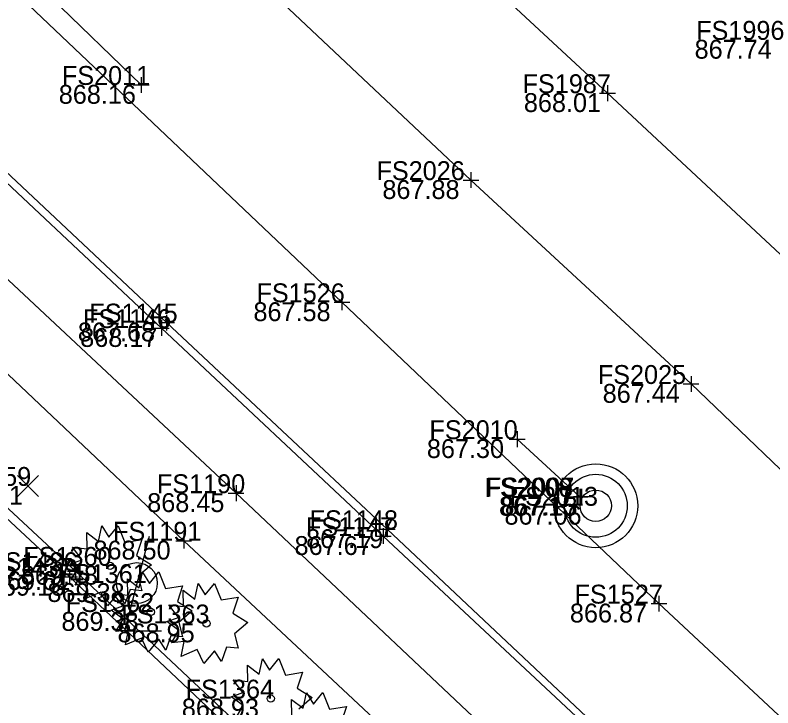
# Model space of a CAD drawing. Extents: x 1479420 to 1479833, y 379731 to 380103.
# Drawn here: x 1479671.72 to 1479719.92, y 379820.06 to 379864.1 of the extents above; entities that cross this region are included whole.
import ezdxf

# ---------------------------------------------------------------- set-up
doc = ezdxf.new("R2010")
doc.units = 0
for name, color, linetype in [('DR_X_Cells', 7, 'Continuous'), ('GK_Drainage_Nodes', 7, 'Continuous'), ('LT_X_Poles', 7, 'Continuous'), ('PM_X_Channelizing_Line', 7, 'Continuous'), ('PM_X_CL_Double_Solid', 7, 'Continuous'), ('PM_X_Lane_Line', 7, 'Continuous'), ('PV_X_Curb', 7, 'Continuous'), ('PV_X_Walk', 7, 'Continuous'), ('SV_X_Random_Point', 7, 'Continuous'), ('SV_X_Shot_Marker', 7, 'Continuous'), ('SV_X_Text_Elevation', 7, 'Continuous'), ('SV_X_Text_Name', 7, 'Continuous'), ('UT_X_Water', 7, 'Continuous'), ('VG_X_Cells', 7, 'Continuous')]:
    doc.layers.add(name, color=color, linetype=linetype)

msp = doc.modelspace()

# ---------------------------------------------------------------- linework, layer by layer
at = {"layer": 'DR_X_Cells'}
for radius in [2.667, 2, 1]:
    msp.add_circle((1479708.658, 379832.907), radius, dxfattribs=at)
at = {"layer": 'GK_Drainage_Nodes'}
for p, q in [((1479708.658, 379834.907), (1479708.658, 379834.907)), ((1479708.658, 379832.907), (1479708.658, 379832.907)), ((1479708.658, 379832.907), (1479708.658, 379832.907)), ((1479708.658, 379832.907), (1479708.658, 379832.907)), ((1479708.658, 379830.907), (1479708.658, 379830.907))]:
    msp.add_line(p, q, dxfattribs=at)
msp.add_circle((1479708.658, 379832.907), 2, dxfattribs=at)
at = {"layer": 'LT_X_Poles'}
msp.add_lwpolyline([(1479680.246, 379830.943), (1479678.671, 379824.958), (1479681.034, 379824.958)], dxfattribs=at)
msp.add_circle((1479679.459, 379827.99), 1.3, dxfattribs=at)
at = {"layer": 'PM_X_Channelizing_Line'}
msp.add_lwpolyline([(1479685.324, 379881.456), (1479709.405, 379859.144), (1479736.1, 379834.256)], dxfattribs=at)
at = {"layer": 'PM_X_CL_Double_Solid'}
msp.add_lwpolyline([(1479794.219, 379768.772), (1479779.093, 379781.771), (1479763.159, 379795.427), (1479746.619, 379810.624), (1479732.239, 379823.873), (1479714.719, 379840.653), (1479700.713, 379853.615), (1479677.934, 379875.066)], dxfattribs=at)
at = {"layer": 'PM_X_Lane_Line'}
for p, q in [((1479679.734, 379859.668), (1479671.915, 379867.241)), ((1479707.65, 379833.476), (1479703.657, 379837.143))]:
    msp.add_line(p, q, dxfattribs=at)
at = {"layer": 'PV_X_Curb'}
for points in [[(1479752.341, 379756.82), (1479734.895, 379773.493), (1479717.229, 379789.662), (1479699.298, 379806.401), (1479688.16, 379794.934), (1479685.526, 379793.897), (1479682.733, 379795.157), (1479681.263, 379797.549), (1479682.493, 379800.746), (1479693.462, 379811.911), (1479675.554, 379828.75), (1479655.832, 379847.057), (1479640.191, 379861.808), (1479628.558, 379849), (1479624.614, 379847.663), (1479622.46, 379848.585), (1479618.996, 379850.857), (1479611.825, 379854.437), (1479601.319, 379856.891), (1479590.521, 379858.038)], [(1479751.933, 379756.628), (1479734.447, 379772.976), (1479716.701, 379789.463), (1479699.4, 379805.742), (1479688.561, 379794.786), (1479685.717, 379793.294), (1479682.291, 379794.8), (1479680.73, 379797.254), (1479682.169, 379801.189), (1479692.652, 379811.907), (1479675.183, 379828.391), (1479655.51, 379846.682), (1479640.151, 379860.926), (1479629.134, 379848.869), (1479624.571, 379847.215), (1479622.228, 379847.911), (1479618.757, 379850.398), (1479611.519, 379853.97), (1479601.347, 379856.369), (1479590.364, 379857.442)], [(1479667.529, 379857.521), (1479681.356, 379844.557), (1479695.384, 379831.416), (1479709.512, 379818.131), (1479724.003, 379804.728), (1479730.662, 379798.272), (1479750.68, 379779.69), (1479759.253, 379771.893), (1479760.555, 379770.78), (1479775.03, 379758.526), (1479788.183, 379747.585), (1479800.537, 379737.251), (1479801.677, 379736.292)], [(1479667.239, 379857.122), (1479681.024, 379844.208), (1479695.135, 379830.978), (1479709.331, 379817.708), (1479723.729, 379804.193), (1479729.719, 379798.6), (1479748.963, 379780.548), (1479759.065, 379771.485), (1479760.185, 379770.473), (1479774.837, 379758.13), (1479787.835, 379747.16), (1479799.962, 379737.109), (1479801.3, 379736.045)]]:
    msp.add_lwpolyline(points, dxfattribs=at)
at = {"layer": 'PV_X_Walk'}
for points in [[(1479760.141, 379765.373), (1479756.862, 379768.221), (1479747.096, 379776.51), (1479736.047, 379786.698), (1479722.324, 379799.574), (1479705.728, 379814.894), (1479685.769, 379833.708), (1479660.411, 379857.395)], [(1479801.031, 379735.954), (1479794.804, 379736.123), (1479792.191, 379733.142), (1479782.769, 379741.06), (1479767.055, 379754.294), (1479759.061, 379761.026), (1479757.309, 379762.481), (1479754.256, 379765.105), (1479744.261, 379773.561), (1479732.859, 379783.688), (1479719.35, 379796.384), (1479703.027, 379811.462), (1479682.443, 379830.686), (1479657.296, 379854.468)]]:
    msp.add_lwpolyline(points, dxfattribs=at)
at = {"layer": 'SV_X_Random_Point'}
for p, q in [((1479671.864, 379833.504), (1479673.198, 379834.839)), ((1479671.864, 379834.839), (1479673.198, 379833.504))]:
    msp.add_line(p, q, dxfattribs=at)
at = {"layer": 'SV_X_Shot_Marker'}
for p, q in [((1479679.734, 379860.168), (1479679.734, 379859.168)), ((1479679.234, 379859.668), (1479680.234, 379859.668)), ((1479679.734, 379859.668), (1479679.734, 379859.668)), ((1479709.405, 379859.644), (1479709.405, 379858.644)), ((1479708.905, 379859.144), (1479709.905, 379859.144)), ((1479709.405, 379859.144), (1479709.405, 379859.144)), ((1479700.713, 379854.115), (1479700.713, 379853.115)), ((1479700.213, 379853.615), (1479701.213, 379853.615)), ((1479700.713, 379853.615), (1479700.713, 379853.615)), ((1479692.509, 379846.347), (1479692.509, 379845.347)), ((1479692.009, 379845.847), (1479693.009, 379845.847)), ((1479692.509, 379845.847), (1479692.509, 379845.847)), ((1479681.356, 379845.057), (1479681.356, 379844.057)), ((1479680.856, 379844.557), (1479681.856, 379844.557)), ((1479681.024, 379844.708), (1479681.024, 379843.708)), ((1479681.356, 379844.557), (1479681.356, 379844.557)), ((1479680.524, 379844.208), (1479681.524, 379844.208)), ((1479681.024, 379844.208), (1479681.024, 379844.208)), ((1479714.719, 379841.153), (1479714.719, 379840.153)), ((1479714.219, 379840.653), (1479715.219, 379840.653)), ((1479714.719, 379840.653), (1479714.719, 379840.653)), ((1479703.657, 379837.643), (1479703.657, 379836.643)), ((1479703.157, 379837.143), (1479704.157, 379837.143)), ((1479703.657, 379837.143), (1479703.657, 379837.143)), ((1479685.769, 379834.208), (1479685.769, 379833.208)), ((1479707.65, 379833.976), (1479707.65, 379832.976)), ((1479707.662, 379833.974), (1479707.662, 379832.974)), ((1479707.74, 379833.993), (1479707.74, 379832.993)), ((1479685.269, 379833.708), (1479686.269, 379833.708)), ((1479685.769, 379833.708), (1479685.769, 379833.708)), ((1479707.15, 379833.476), (1479708.15, 379833.476)), ((1479707.162, 379833.474), (1479708.162, 379833.474)), ((1479707.24, 379833.493), (1479708.24, 379833.493)), ((1479707.65, 379833.476), (1479707.65, 379833.476)), ((1479707.662, 379833.474), (1479707.662, 379833.474)), ((1479707.74, 379833.493), (1479707.74, 379833.493)), ((1479695.384, 379831.916), (1479695.384, 379830.916)), ((1479694.884, 379831.416), (1479695.884, 379831.416)), ((1479695.135, 379831.478), (1479695.135, 379830.478)), ((1479695.384, 379831.416), (1479695.384, 379831.416)), ((1479682.443, 379831.186), (1479682.443, 379830.186)), ((1479694.635, 379830.978), (1479695.635, 379830.978)), ((1479695.135, 379830.978), (1479695.135, 379830.978)), ((1479681.943, 379830.686), (1479682.943, 379830.686)), ((1479682.443, 379830.686), (1479682.443, 379830.686)), ((1479675.554, 379829.25), (1479675.554, 379828.25)), ((1479675.054, 379828.75), (1479676.054, 379828.75)), ((1479675.183, 379828.891), (1479675.183, 379827.891)), ((1479675.554, 379828.75), (1479675.554, 379828.75)), ((1479674.683, 379828.391), (1479675.683, 379828.391)), ((1479675.183, 379828.391), (1479675.183, 379828.391)), ((1479712.672, 379827.186), (1479712.672, 379826.186)), ((1479712.172, 379826.686), (1479713.172, 379826.686)), ((1479712.672, 379826.686), (1479712.672, 379826.686))]:
    msp.add_line(p, q, dxfattribs=at)
at = {"layer": 'UT_X_Water'}
msp.add_lwpolyline([(1479473.217, 380054.881), (1479498.741, 380029.974), (1479514.505, 380014.086), (1479533.448, 379996.735), (1479556.003, 379974.319), (1479574.861, 379956.271), (1479584.403, 379947.432), (1479599.597, 379932.819), (1479630.106, 379903.783), (1479644.769, 379889.722), (1479654.209, 379882.356), (1479664.266, 379872.629), (1479692.509, 379845.847), (1479712.672, 379826.686), (1479730.739, 379809.85), (1479753.15, 379788.309), (1479771.842, 379770.542), (1479781.678, 379761.101)], dxfattribs=at)
at = {"layer": 'VG_X_Cells'}
for points in [[(1479677.672, 379830.9), (1479678.277, 379831.635), (1479678.692, 379830.581), (1479679.784, 379830.761), (1479679.445, 379829.75), (1479680.39, 379829.155), (1479679.534, 379828.42), (1479679.784, 379827.506), (1479679.03, 379827.575), (1479678.705, 379826.661), (1479678.277, 379827.353), (1479677.599, 379826.536), (1479677.17, 379827.423), (1479676.15, 379826.993), (1479676.342, 379827.935), (1479675.53, 379827.851), (1479676.004, 379828.641), (1479675.235, 379829.21), (1479675.974, 379829.473), (1479675.367, 379830.276), (1479676.299, 379830.166), (1479676.269, 379831.205), (1479677.022, 379830.636), (1479677.229, 379831.621), (1479677.672, 379830.9)], [(1479680.262, 379827.962), (1479680.867, 379828.697), (1479681.282, 379827.643), (1479682.374, 379827.823), (1479682.035, 379826.812), (1479682.98, 379826.217), (1479682.124, 379825.482), (1479682.374, 379824.568), (1479681.62, 379824.637), (1479681.295, 379823.723), (1479680.867, 379824.415), (1479680.189, 379823.598), (1479679.76, 379824.485), (1479678.74, 379824.055), (1479678.932, 379824.997), (1479678.12, 379824.913), (1479678.594, 379825.703), (1479677.825, 379826.272), (1479678.564, 379826.535), (1479677.957, 379827.338), (1479678.889, 379827.228), (1479678.859, 379828.267), (1479679.612, 379827.698), (1479679.819, 379828.683), (1479680.262, 379827.962)], [(1479683.803, 379827.235), (1479684.408, 379827.97), (1479684.823, 379826.917), (1479685.915, 379827.097), (1479685.576, 379826.085), (1479686.521, 379825.49), (1479685.665, 379824.755), (1479685.915, 379823.842), (1479685.161, 379823.91), (1479684.836, 379822.997), (1479684.408, 379823.689), (1479683.73, 379822.872), (1479683.301, 379823.759), (1479682.281, 379823.329), (1479682.473, 379824.27), (1479681.661, 379824.187), (1479682.135, 379824.977), (1479681.366, 379825.545), (1479682.105, 379825.809), (1479681.498, 379826.612), (1479682.43, 379826.502), (1479682.4, 379827.54), (1479683.153, 379826.972), (1479683.36, 379827.957), (1479683.803, 379827.235)], [(1479687.895, 379822.457), (1479688.5, 379823.192), (1479688.915, 379822.138), (1479690.007, 379822.318), (1479689.668, 379821.307), (1479690.613, 379820.712), (1479689.757, 379819.977)], [(1479685.753, 379819.408), (1479686.227, 379820.198), (1479685.458, 379820.767), (1479686.197, 379821.03), (1479685.59, 379821.833), (1479686.522, 379821.723), (1479686.492, 379822.762), (1479687.245, 379822.193), (1479687.452, 379823.178), (1479687.895, 379822.457)], [(1479689.32, 379819.557), (1479689.29, 379820.596), (1479690.043, 379820.027), (1479690.25, 379821.012), (1479690.693, 379820.291)], [(1479690.693, 379820.291), (1479691.298, 379821.026), (1479691.713, 379819.972), (1479692.805, 379820.152), (1479692.466, 379819.141)]]:
    msp.add_lwpolyline(points, dxfattribs=at)
for centre in [(1479677.756, 379829.09), (1479680.346, 379826.152), (1479683.887, 379825.426), (1479687.979, 379820.647)]:
    msp.add_circle(centre, 0.23, dxfattribs=at)

# ---------------------------------------------------------------- texts
at = {"layer": 'SV_X_Text_Elevation'}
for s, p in [('867.74', (1479714.947, 379861.336)), ('868.16', (1479674.491, 379858.468)), ('868.01', (1479704.085, 379857.944)), ('867.88', (1479695.082, 379852.415)), ('867.58', (1479686.878, 379844.647)), ('867.68', (1479675.706, 379843.357)), ('868.17', (1479675.856, 379843.008)), ('867.44', (1479709.097, 379839.453)), ('867.30', (1479697.912, 379835.943)), ('869.51', (1479667.305, 379832.971)), ('868.45', (1479680.119, 379832.508)), ('867.15', (1479702.501, 379832.276)), ('867.15', (1479702.513, 379832.274)), ('867.13', (1479702.591, 379832.293)), ('867.06', (1479702.847, 379831.707)), ('867.19', (1479690.226, 379830.216)), ('867.67', (1479689.494, 379829.778)), ('868.50', (1479676.698, 379829.486)), ('869.48', (1479672.079, 379827.89)), ('869.61', (1479670.309, 379827.55)), ('869.18', (1479669.987, 379827.191)), ('869.38', (1479673.771, 379826.79)), ('866.87', (1479707.013, 379825.486)), ('869.38', (1479674.659, 379824.952)), ('868.95', (1479678.229, 379824.225)), ('868.93', (1479682.321, 379819.447))]:
    msp.add_text(s, height=1.2, dxfattribs=at).set_placement(p)
at = {"layer": 'SV_X_Text_Name'}
for s, p in [('FS1996', (1479715.042, 379862.536)), ('FS2011', (1479674.689, 379859.668)), ('FS1987', (1479704.001, 379859.144)), ('FS2026', (1479694.704, 379853.615)), ('FS1526', (1479687.068, 379845.847)), ('FS1146', (1479676.027, 379844.208)), ('FS1145', (1479676.435, 379844.557)), ('FS2025', (1479708.786, 379840.653)), ('FS2010', (1479698.074, 379837.143)), ('FS1359', (1479667.118, 379834.171)), ('FS1190', (1479680.734, 379833.708)), ('FS2009', (1479701.575, 379833.476)), ('FS2008', (1479701.587, 379833.474)), ('FS2007', (1479701.674, 379833.493)), ('FS2013', (1479703.179, 379832.907)), ('FS1148', (1479690.453, 379831.416)), ('FS1191', (1479677.946, 379830.686)), ('FS1147', (1479690.214, 379830.978)), ('FS1436', (1479670.065, 379828.75)), ('FS1360', (1479672.23, 379829.09)), ('FS1437', (1479669.77, 379828.391)), ('FS1361', (1479674.47, 379827.99)), ('FS1527', (1479707.306, 379826.686)), ('FS1362', (1479674.934, 379826.152)), ('FS1363', (1479678.465, 379825.425)), ('FS1364', (1479682.567, 379820.647))]:
    msp.add_text(s, height=1.2, dxfattribs=at).set_placement(p)

doc.saveas('drawing.dxf')
